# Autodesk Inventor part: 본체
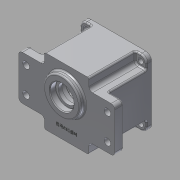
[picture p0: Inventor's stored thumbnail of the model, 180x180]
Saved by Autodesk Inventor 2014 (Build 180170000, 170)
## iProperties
Created: 2015-07
Part Number: 본체
Material: 알루미늄 6061
Document SubType Name: Modeling
Designer: Administrator
Density: 2.71 g/cm^3
Appearance: 알루미늄 - 평지
Mass: 705.387 g
Surface Area: 672.972 cm^2
Volume: 260.29 cm^3
Author: Administrator
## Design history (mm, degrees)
sketch "스케치1"
  geometry: L1 (45, 45)-(-45, 45); L2 (-45, 45)-(-45, -45); L3 (-45, -45)-(45, -45); L4 (45, -45)-(45, 45); L5 (45, 45)-(-45, -45); L6 (-45, 45)-(45, -45); 1 further point
  constraints: 12 end point, 2 midpoint, 2 parallel, 1 horizontal, 1 perpendicular
  dimensions: "d0" = 90 distance of L3.end L2.end; "d1" = 90 distance of L2.end L1.end
extrude "돌출1" new body sketch "스케치1" distance "d2" = 70; taper "d3" = 0 deg
sketch "스케치2"
  geometry: L1 (45, 45)-(30, 45); L2 (30, 45)-(30, 30); L3 (30, 30)-(45, 30); L4 (45, 30)-(45, 45); L5 (-45, 45)-(-30, 45); L6 (-30, 45)-(-30, 30); L7 (-30, 30)-(-45, 30); L8 (-45, 30)-(-45, 45); L9 (-45, -45)-(-30, -45); L10 (-30, -45)-(-30, -30); L11 (-30, -30)-(-45, -30); L12 (-45, -30)-(-45, -45); L13 (45, -45)-(30, -45); L14 (30, -45)-(30, -30); L15 (30, -30)-(45, -30); L16 (45, -30)-(45, -45); 1 further point
  constraints: 32 end point, 8 parallel, 4 horizontal, 4 perpendicular
  dimensions: "d4" = 15 distance of L3.end L2.end; "d5" = 15 distance of L2.end L1.end; "d6" = 15 distance of L6.end L7.end; "d7" = 15 distance of L5.end L6.end; "d8" = 15 distance of L11.end L10.end; "d9" = 15 distance of L10.end L9.end; "d10" = 15 distance of L14.end L15.end; "d11" = 15 distance of L15.end L13.start
extrude "돌출2" cut sketch "스케치2" distance "d12" = 63; taper "d13" = 0 deg
node "작업 평면1"
sketch "스케치3"
  geometry: L1 (65, 30)-(-65, 30); L2 (-65, 30)-(-65, -30); L3 (-65, -30)-(65, -30); L4 (65, -30)-(65, 30); L5 (65, 30)-(-65, -30); L6 (-65, 30)-(65, -30); 1 further point
  constraints: 12 end point, 2 midpoint, 2 parallel, 1 horizontal, 1 perpendicular
  dimensions: "d15" = 130 distance of L3.end L2.end; "d16" = 60 distance of L2.end L1.end
extrude "돌출3" join sketch "스케치3" distance "d17" = 12; taper "d18" = 0 deg
sketch "스케치4"
  geometry: 5 further points
  constraints: 2 horizontal alignment, 2 vertical alignment
  dimensions: "d19" = 74 distance of point (37, 37) point (-37, 37); "d20" = 37 horizontal distance of point (0, 0) point (-37, 37); "d21" = 74 distance of point (-37, -37) point (-37, 37); "d22" = 37 horizontal distance of point (0, 0) point (-37, -37)
hole "구멍1" sketch "스케치4" at (-37, 37), (-37, -37), (37, -37), (37, 37) diameter "d23" = 7; stored, may be unused: countersink angle "d27" = 90 deg, drill point angle "d29" = 118 deg; dims "d24" = 6, "d25" = 4, "d26" = 2, "d28" = 8
sketch "스케치5"
  geometry: 5 further points
  constraints: 2 horizontal alignment, 2 vertical alignment
  dimensions: "d30" = 110 distance of point (55, -17.5) point (-55, -17.5); "d31" = 55 horizontal distance of point (0, 0) point (-55, -17.5); "d32" = 35 distance of point (-55, 17.5) point (-55, -17.5); "d33" = 17.5 vertical distance of point (0, 0) point (-55, 17.5)
hole "구멍2" sketch "스케치5" at (-55, 17.5), (-55, -17.5), (55, -17.5), (55, 17.5) diameter "d34" = 9; stored, may be unused: countersink angle "d38" = 90 deg, drill point angle "d40" = 118 deg; dims "d35" = 6, "d36" = 4, "d37" = 2, "d39" = 8
sketch "스케치6"
  geometry: C1 r 40 at (0, 0); 1 further point
  constraints: 1 centre point, 1 coincident
  dimensions: "d41" = 80 diameter of C1
extrude "돌출4" cut sketch "스케치6" distance "d42" = 9; taper "d43" = 0 deg
sketch "스케치7"
  geometry: C1 r 40 at (0, 0) reference; C2 r 39 at (0, 0)
  constraints: 1 centre point, 1 coincident
  dimensions: "d44" = 78 diameter of C2
extrude "돌출5" cut sketch "스케치7" distance "d45" = 52; taper "d46" = 0 deg
sketch "스케치8"
  geometry: C1 r 25 at (0, 11); 1 further point
  constraints: 1 centre point, 1 vertical alignment
  dimensions: "d47" = 11 distance of C1.centre point (0, 0); "d48" = 50 diameter of C1
extrude "돌출6" join sketch "스케치8" distance "d49" = 7; taper "d50" = 0 deg
sketch "스케치9"
  geometry: C1 r 25 at (0, 0) reference; 2 further points
  constraints: 1 coincident
hole "구멍3" sketch "스케치9" at (0, 0) diameter "d51" = 25; stored, may be unused: countersink angle "d55" = 90 deg, drill point angle "d57" = 0 deg; dims "d52" = 6, "d53" = 32, "d54" = 8, "d56" = 13
sketch "스케치11"
  geometry: C1 r 17.5 at (0, -11) reference; C2 r 20.5 at (0, -11)
  constraints: 1 centre point, 1 coincident
  dimensions: "d61" = 41 diameter of C2
extrude "돌출8" join sketch "스케치11" distance "d62" = 7; taper "d63" = 0 deg
sketch "스케치12"
  geometry: C1 r 39 at (0, 0) reference; C2 r 14 at (0, 20)
  constraints: 1 centre point, 1 vertical alignment
  dimensions: "d64" = 28 diameter of C2; "d65" = 20 distance of C1.centre C2.centre
extrude "돌출9" join sketch "스케치12" distance "d66" = 7; taper "d67" = 0 deg
sketch "스케치13"
  geometry: C1 r 11 at (0, 20); A1 r 14 centre (0, 20) between (7.402, 8.117) and (-7.402, 8.117) reference; 1 further point
  constraints: 1 centre point, 1 coincident
  dimensions: "d68" = 22 diameter of C1
extrude "돌출10" cut sketch "스케치13" distance "d69" = 7; taper "d70" = 0 deg
sketch "스케치14"
  geometry: C1 r 11 at (0, 0) reference; C2 r 9.5 at (0, 0); 1 further point
  constraints: 1 centre point, 1 coincident
  dimensions: "d71" = 19 diameter of C2
extrude "돌출11" cut sketch "스케치14" distance "d72" = 1; taper "d73" = 0 deg
sketch "스케치15"
  geometry: C1 r 12.5 at (0, 0) reference; C2 r 17.5 at (0, 0); 1 further point
  constraints: 1 centre point, 1 coincident
  dimensions: "d74" = 35 diameter of C2
extrude "돌출12" cut sketch "스케치15" distance "d75" = 10; taper "d76" = 0 deg
sketch "스케치16"
  geometry: L1 (0, 0)-(-24.749, -24.749); L2 (0, 0)-(-35, 0); L3 (-21.758, -27.415)-(-24.603, -30.26); L4 (-25.314, -30.971)-(-27.808, -33.464); L5 (-27.415, -21.758)-(-30.26, -24.603); L6 (-30.971, -25.314)-(-34.882, -29.225); C1 r 4 at (-24.749, -24.749); A1 r 39 centre (0, 0) between (-24.603, -30.26) and (-30.26, -24.603) reference; A2 r 40 centre (0, 0) between (-25.314, -30.971) and (-30.971, -25.314) reference; A3 r 35 centre (0, 0) between (-24.749, -24.749) and (-35, 0)
  constraints: 12 end point, 8 point on circle, 4 parallel, 4 tangent, 2 centre point, 2 coincident, 1 horizontal
  dimensions: "d77" = 70 diameter of A3; "d78" = 45 deg angle of L2 L1; "d79" = 4 radius of C1
extrude "돌출13" join sketch "스케치16" stored distance "d80" = 10; taper "d81" = 0 deg
sketch "스케치17"
  geometry: A1 r 4 centre (-24.749, -24.749) between (-21.763, -27.411) and (-27.411, -21.763) reference; A2 r 4 centre (-24.749, 24.749) between (-27.411, 21.763) and (-21.763, 27.411) reference; A3 r 4 centre (24.749, 24.749) between (21.763, 27.411) and (27.411, 21.763) reference; A4 r 4 centre (24.749, -24.749) between (27.411, -21.763) and (21.763, -27.411) reference; 4 further points
  constraints: 4 coincident
hole "구멍4" sketch "스케치17" at (-24.749, 24.749), (-24.749, -24.749), (24.749, -24.749), (24.749, 24.749) diameter "d85" = 3.459; stored, may be unused: countersink angle "d89" = 90 deg, drill point angle "d91" = 118 deg; dims "d86" = 12, "d87" = 32, "d88" = 8, "d90" = 15
fillet "모깎기1" dims "d92" = 0.3
fillet "모깎기2" dims "d93" = 3.5
fillet "모깎기3" dims "d94" = 2
fillet "모깎기4" dims "d95" = 3
fillet "모깎기5" dims "d96" = 2
chamfer "모따기1" distance "d97" = 1; stored, may be unused: second distance "d98" = 2, angle "d99" = 45 deg
chamfer "모따기2" distance "d100" = 1; stored, may be unused: second distance "d101" = 2, angle "d102" = 45 deg
fillet "모깎기6" dims "d103" = 0.3
fillet "모깎기7" dims "d104" = 2
fillet "모깎기8" dims "d105" = 5
fillet "모깎기9" dims "d106" = 8
fillet "모깎기10" dims "d107" = 5
fillet "모깎기11" dims "d108" = 2
sketch "스케치18"
  geometry: L1 (-28, -45)-(28, -45) reference; C1 r 25 at (0, 11) reference; 2 further points
  constraints: 1 vertical alignment, 1 other
  dimensions: "d109" = 15 distance from line of point (0, -30) L1
feature "엠보싱1" sketch "스케치18" dims "d8" = 15, "d9" = 15, "d110" = 0.5, "d111" = 0
fillet "모깎기12" dims "d112" = 2
fillet "모깎기13" dims "d113" = 2
node "솔리드1"
pattern_circular "원형 패턴1" dims angle "d83" = 360 deg
other parameters: "d14" = -12
